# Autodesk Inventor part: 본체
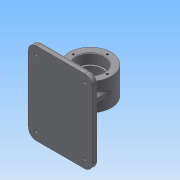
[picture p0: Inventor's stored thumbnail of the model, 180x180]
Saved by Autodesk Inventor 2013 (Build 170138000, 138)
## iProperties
Created: 2019-09
Part Number: 본체
Material: 일반
Document SubType Name: Modeling
Designer: Administrator
Density: 1 g/cm^3
Author: Administrator
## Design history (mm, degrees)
sketch "스케치1"
  geometry: C1 r 32 at (0, 0); 1 further point
  constraints: 1 centre point, 1 coincident
  dimensions: "d0" = 64 diameter of C1
extrude "돌출1" new body sketch "스케치1" stored distance "d1" = 42; taper "d2" = 0 deg
sketch "스케치2"
  geometry: C1 r 32 at (0, 0) reference; C2 r 21 at (0, 0)
  constraints: 1 centre point, 1 coincident
  dimensions: "d3" = 42 diameter of C2
extrude "돌출2" cut sketch "스케치2" distance "d4" = 15; taper "d5" = 0 deg
hole "구멍1" diameter "d8" = 36; stored, may be unused: countersink angle "d12" = 90 deg, drill point angle "d14" = 0 deg; dims "d6" = 10, "d7" = 10, "d9" = 6, "d10" = 42, "d11" = 15, "d13" = 8
sketch "스케치3"
  geometry: C1 r 21 at (0, 0) reference; 1 further point
  constraints: 1 vertical alignment
  dimensions: "d15" = 26 distance of C1.centre point (0, 26)
hole "구멍2" sketch "스케치3" at (0, 26) diameter "d16" = 3.242; stored, may be unused: countersink angle "d20" = 90 deg, drill point angle "d22" = 118 deg; dims "d17" = 8, "d18" = 42, "d19" = 15, "d21" = 10
node "작업 평면1"
sketch "스케치4"
  geometry: L1 (-36, 63)-(62, 63); L2 (62, 63)-(62, -63); L3 (62, -63)-(-36, -63); L4 (-36, -63)-(-36, 63); 1 further point
  constraints: 8 end point, 2 parallel, 1 horizontal, 1 perpendicular
  dimensions: "d27" = 98 distance of L1.start L1.end; "d29" = 126 distance of L3.end L1.start; "d30" = 62 distance from line of L2 point (0, 0); "d31" = 63 distance from line of L3 point (0, 0)
extrude "돌출3" join sketch "스케치4" distance "d32" = 9; taper "d33" = 0 deg
sketch "스케치5"
  geometry: L1 (32, 4)-(-32, 4); L2 (-32, 4)-(-32, -4); L3 (-32, -4)-(32, -4); L4 (32, -4)-(32, 4); L5 (4, 17)-(-4, 17); L6 (-4, 17)-(-4, -17); L7 (-4, -17)-(4, -17); L8 (4, -17)-(4, 17); 5 further points
  constraints: 16 end point, 4 midpoint, 4 parallel, 2 horizontal, 2 horizontal alignment, 2 perpendicular, 2 vertical alignment
  dimensions: "d34" = 8 distance of L3.end L1.start; "d36" = 8 distance of L5.start L5.end; "d37" = 34 distance of L5.end L6.end; "d38" = 64 distance of L1.start L1.end
extrude "돌출4" join sketch "스케치5" stored distance "d39" = 9; taper "d40" = 0 deg
fillet "모깎기1" dims "d41" = 12
sketch "스케치6"
  geometry: A1 r 12 centre (50, 51) between (62, 51) and (50, 63) reference; A2 r 12 centre (-24, 51) between (-24, 63) and (-36, 51) reference; 3 further points
  constraints: 2 coincident
hole "구멍3" sketch "스케치6" at (-24, 51), (50, 51) diameter "d42" = 4.5; stored, may be unused: countersink angle "d46" = 90 deg, drill point angle "d48" = 0 deg; dims "d43" = 8, "d44" = 8, "d45" = 4.4, "d47" = 10
fillet "모깎기2" dims "d49" = 0.3
chamfer "모따기1" distance "d50" = 1; stored, may be unused: second distance "d51" = 2, angle "d52" = 45 deg
fillet "모깎기3" dims "d53" = 3
fillet "모깎기4" dims "d54" = 3
fillet "모깎기5" dims "d55" = 3
sketch "스케치7"
  geometry: L1 (62, -51)-(62, 51) reference; 2 further points
  constraints: 1 horizontal alignment, 1 other
  dimensions: "d56" = 10 distance from line of point (52, 0) L1
feature "엠보싱1" sketch "스케치7" dims "d57" = 0.5, "d58" = 0
node "솔리드1"
pattern_circular "원형 패턴1" dims angle "d24" = 360 deg
mirror "대칭1"
mirror "대칭2"
other parameters: "d26" = -59
